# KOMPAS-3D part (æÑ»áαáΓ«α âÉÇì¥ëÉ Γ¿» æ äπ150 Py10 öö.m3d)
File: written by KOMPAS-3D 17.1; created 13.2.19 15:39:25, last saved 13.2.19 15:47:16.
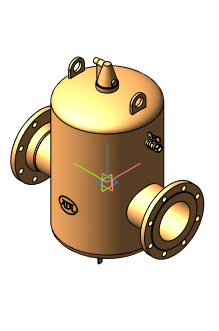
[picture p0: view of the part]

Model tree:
1. Операция без истории:4  (with: Сечение модели:1)

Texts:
  Точка начала. Х
  Точка начала. Y
  Точка начала. Z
